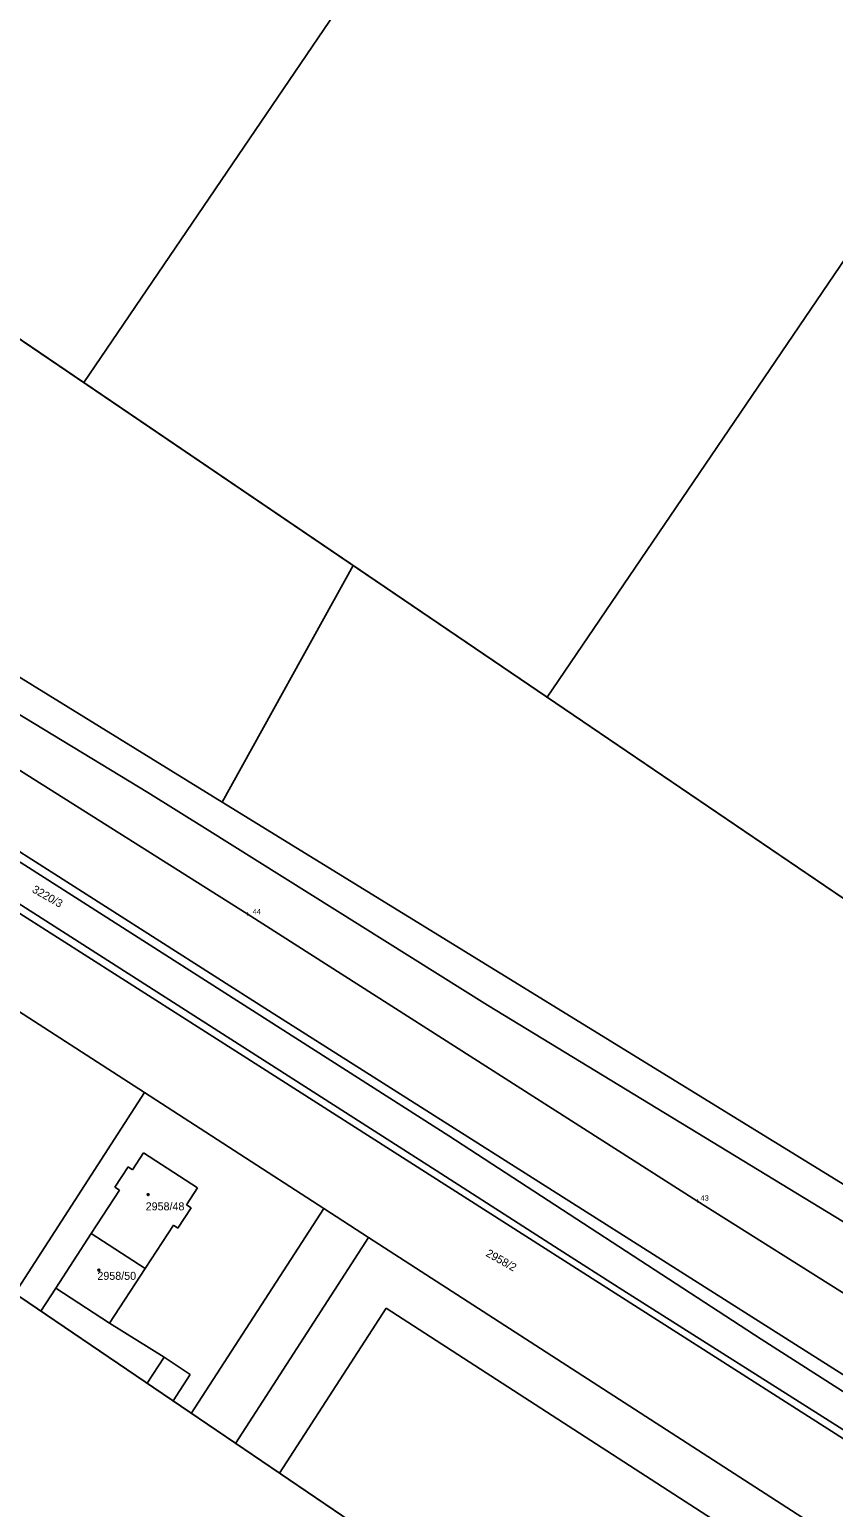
# Model space of a CAD drawing. Extents: x -621058 to -620110, y -1122807 to -1122030.
# Drawn here: x -620724.3 to -620573.6, y -1122540.7 to -1122263.7 of the extents above; entities that cross this region are included whole.
import ezdxf

# ---------------------------------------------------------------- set-up
doc = ezdxf.new("R2010")
doc.units = 0
for name, color, linetype in [('060601_EOV', 7, 'Continuous'), ('BODY', 7, 'Continuous'), ('BODY POPIS', 7, 'Continuous'), ('RÁMY', 7, 'Continuous'), ('Vrstva 53', 7, 'Continuous'), ('Vrstva 55', 7, 'Continuous'), ('Vrstva 56', 7, 'Continuous'), ('Vrstva 57', 7, 'Continuous')]:
    doc.layers.add(name, color=color, linetype=linetype)

msp = doc.modelspace()

# ---------------------------------------------------------------- linework, layer by layer
at = {"layer": '060601_EOV'}
msp.add_lwpolyline([(-620538.89, -1122521.21), (-620599.21, -1122483.22), (-620683.52, -1122429.44), (-620756.33, -1122383.52), (-620765.8, -1122398.39), (-620784.65, -1122386.39), (-620822.22, -1122362.42), (-620817.53, -1122355.08), (-620826.41, -1122348.08), (-620839.92, -1122337.94), (-620848.84, -1122332), (-620848.83, -1122331.99)], dxfattribs=at)
at = {"layer": 'RÁMY'}
for points in [[(-620717.54, -1122148.04), (-620630.68, -1122207.04), (-620714.11, -1122329.88), (-620800.97, -1122270.89)], [(-620974.7, -1122152.91), (-620192.94, -1122683.83), (-620276.37, -1122806.68), (-621058.13, -1122275.76)], [(-620630.68, -1122207.04), (-620543.82, -1122266.03), (-620627.25, -1122388.87), (-620714.11, -1122329.88)], [(-620887.83, -1122211.9), (-620192.94, -1122683.83), (-620276.37, -1122806.68), (-620971.26, -1122334.75)], [(-620543.82, -1122266.03), (-620456.95, -1122325.02), (-620540.39, -1122447.87), (-620627.25, -1122388.87)]]:
    msp.add_lwpolyline(points, close=True, dxfattribs=at)
at = {"layer": 'Vrstva 53'}
for p, q in [((-620748.53, -1122378.52), (-620702.13, -1122406.7)), ((-620702.13, -1122406.7), (-620691.02, -1122413.66)), ((-620679.51, -1122447.56), (-620741.46, -1122408.09)), ((-620691.02, -1122413.66), (-620638.48, -1122446.57)), ((-620545.92, -1122532.26), (-620679.51, -1122447.56)), ((-620638.48, -1122446.57), (-620552.09, -1122499.2))]:
    msp.add_line(p, q, dxfattribs=at)
at = {"layer": 'Vrstva 55'}
for p, q in [((-620866.03, -1122298.98), (-620688.16, -1122408.5)), ((-620684.91, -1122455.63), (-620825.92, -1122365.89)), ((-620663.64, -1122364.16), (-620688.16, -1122408.5)), ((-620645.72, -1122471.03), (-620807.67, -1122367.84)), ((-620748.53, -1122378.52), (-620702.13, -1122406.7)), ((-620702.13, -1122406.7), (-620691.02, -1122413.66)), ((-620741.46, -1122408.09), (-620679.51, -1122447.56)), ((-620688.16, -1122408.5), (-620548.9, -1122494.24)), ((-620691.02, -1122413.66), (-620638.48, -1122446.57)), ((-620702.74, -1122462.95), (-620757.34, -1122427.68)), ((-620545.92, -1122532.26), (-620679.51, -1122447.56)), ((-620638.48, -1122446.57), (-620552.09, -1122499.2)), ((-620557.45, -1122536.96), (-620684.91, -1122455.63)), ((-620727.06, -1122500.6), (-620702.74, -1122462.95)), ((-620669.14, -1122484.66), (-620702.74, -1122462.95)), ((-620587.17, -1122509.18), (-620645.72, -1122471.03)), ((-620705.81, -1122476.87), (-620708.28, -1122480.69)), ((-620704.97, -1122477.41), (-620705.81, -1122476.87)), ((-620702.93, -1122474.27), (-620704.97, -1122477.41)), ((-620702.93, -1122474.27), (-620692.81, -1122480.83)), ((-620712.73, -1122489.39), (-620707.44, -1122481.23)), ((-620708.28, -1122480.69), (-620707.44, -1122481.23)), ((-620692.81, -1122480.83), (-620694.86, -1122483.99)), ((-620694.01, -1122484.54), (-620696.48, -1122488.34)), ((-620694.86, -1122483.99), (-620694.01, -1122484.54)), ((-620693.96, -1122523.08), (-620669.14, -1122484.66)), ((-620660.74, -1122490.09), (-620669.14, -1122484.66)), ((-620697.33, -1122487.79), (-620702.63, -1122495.93)), ((-620696.48, -1122488.34), (-620697.33, -1122487.79)), ((-620719.36, -1122499.62), (-620712.73, -1122489.39)), ((-620712.73, -1122489.39), (-620702.63, -1122495.93)), ((-620660.74, -1122490.09), (-620685.68, -1122528.7)), ((-620576.58, -1122544.45), (-620660.74, -1122490.09)), ((-620702.63, -1122495.93), (-620709.28, -1122506.15)), ((-620719.36, -1122499.62), (-620722.14, -1122503.94)), ((-620677.41, -1122534.31), (-620657.43, -1122503.38)), ((-620657.43, -1122503.38), (-620581.67, -1122552.32)), ((-620699.07, -1122512.52), (-620709.28, -1122506.15)), ((-620511.29, -1122557.64), (-620587.17, -1122509.18)), ((-620694.2, -1122515.81), (-620699.07, -1122512.52)), ((-620697.39, -1122520.75), (-620694.2, -1122515.81))]:
    msp.add_line(p, q, dxfattribs=at)
at = {"layer": 'Vrstva 56'}
for p, q in [((-620810.36, -1122373.73), (-620648.08, -1122477.56)), ((-620648.08, -1122477.56), (-620625, -1122492.37)), ((-620625, -1122492.37), (-620613.12, -1122500)), ((-620709.28, -1122506.15), (-620719.36, -1122499.62)), ((-620570.69, -1122526.84), (-620613.12, -1122500)), ((-620699.07, -1122512.52), (-620702.26, -1122517.44))]:
    msp.add_line(p, q, dxfattribs=at)
at = {"layer": 'Vrstva 57'}
for centre in [(-620702.05, -1122482.08), (-620711.29, -1122496.23)]:
    msp.add_circle(centre, 0.175, dxfattribs=at)

# ---------------------------------------------------------------- texts
at = {"layer": 'BODY'}
for p in [(-620683.86, -1122429.94), (-620599.55, -1122483.72)]:
    msp.add_text('+', height=1, dxfattribs=at).set_placement(p)
at = {"layer": 'BODY POPIS'}
for s, p in [('44', (-620682.47, -1122429.54)), ('43', (-620598.54, -1122483.21))]:
    msp.add_text(s, height=1, dxfattribs=at).set_placement(p)
at = {"layer": 'Vrstva 57'}
for s, p in [('3220/3', (-620723.93, -1122425.31)), ('2958/2', (-620638.9, -1122493.5))]:
    msp.add_text(s, height=1.5, rotation=330.3, dxfattribs=at).set_placement(p)
for s, p in [('2958/48', (-620702.51, -1122485.03)), ('2958/50', (-620711.56, -1122498.05))]:
    msp.add_text(s, height=1.5, dxfattribs=at).set_placement(p)

doc.saveas('drawing.dxf')
